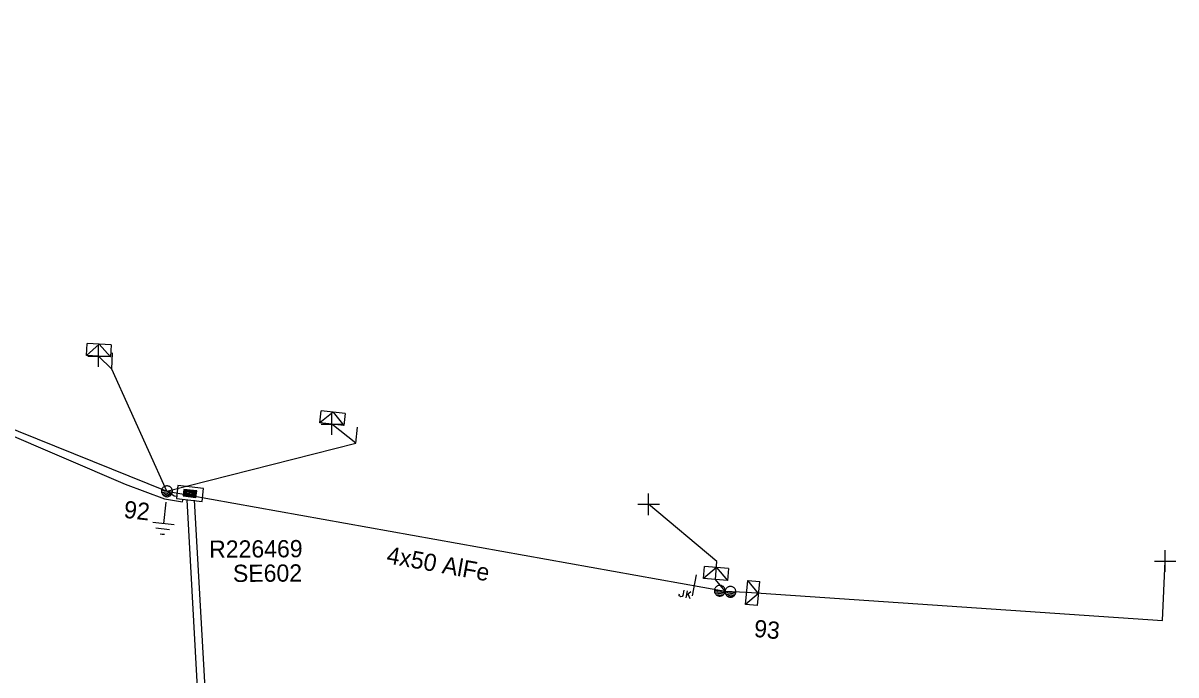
# Model space of a CAD drawing. Extents: x -544780 to -541582, y -1198995 to -1196551.
# Drawn here: x -542510.9 to -542443.9, y -1198250.4 to -1198212.6 of the extents above; entities that cross this region are included whole.
import ezdxf

# ---------------------------------------------------------------- set-up
doc = ezdxf.new("R2010")
doc.units = 0
for name, color, linetype in [('Vrstva 1', 7, 'Continuous'), ('Vrstva 13', 7, 'Continuous'), ('Vrstva 14', 7, 'Continuous'), ('Vrstva 15', 7, 'Continuous'), ('Vrstva 18', 7, 'Continuous'), ('Vrstva 2', 7, 'Continuous'), ('Vrstva 28', 7, 'Continuous'), ('Vrstva 29', 7, 'Continuous'), ('Vrstva 30', 7, 'Continuous'), ('Vrstva 31', 7, 'Continuous'), ('Vrstva 34', 7, 'Continuous'), ('Vrstva 5', 7, 'Continuous'), ('Vrstva 54', 7, 'Continuous'), ('Vrstva 59', 7, 'Continuous'), ('Vrstva 8', 7, 'Continuous'), ('Vrstva 9', 7, 'Continuous')]:
    doc.layers.add(name, color=color, linetype=linetype)

# ---------------------------------------------------------------- blocks, each defined once
blk = doc.blocks.new('NN440')
at = {"layer": 'Vrstva 2'}
for points in [[(0.63, 0), (0.63, 0.06), (0.62, 0.13), (0.6, 0.19), (0.58, 0.25), (0.55, 0.31), (0.51, 0.37), (0.47, 0.42), (0.42, 0.46), (0.37, 0.51), (0.32, 0.54), (0.26, 0.57), (0.2, 0.59), (0.13, 0.61), (0.07, 0.62), (0, 0.63), (-0.06, 0.62), (-0.13, 0.61), (-0.19, 0.59), (-0.26, 0.57), (-0.31, 0.54), (-0.37, 0.51), (-0.42, 0.46), (-0.47, 0.42), (-0.51, 0.37), (-0.54, 0.31), (-0.57, 0.25), (-0.6, 0.19), (-0.62, 0.13), (-0.63, 0.06), (-0.63, 0), (-0.63, -0.07), (-0.62, -0.14), (-0.6, -0.2), (-0.57, -0.26), (-0.54, -0.32), (-0.51, -0.37), (-0.47, -0.43), (-0.42, -0.47), (-0.37, -0.51), (-0.31, -0.55), (-0.26, -0.58), (-0.19, -0.6), (-0.13, -0.62), (-0.06, -0.63), (0, -0.63), (0.07, -0.63), (0.13, -0.62), (0.2, -0.6), (0.26, -0.58), (0.32, -0.55), (0.37, -0.51), (0.42, -0.47), (0.47, -0.43), (0.51, -0.37), (0.55, -0.32), (0.58, -0.26), (0.6, -0.2), (0.62, -0.14), (0.63, -0.07), (0.63, 0)], [(-0.63, 0), (0.63, 0)], [(-0.6, -0.18), (0.57, -0.18)], [(-0.51, -0.32), (0.5, -0.32)], [(-0.37, -0.47), (0.35, -0.47)]]:
    blk.add_lwpolyline(points, dxfattribs=at)
blk = doc.blocks.new('NN450')
at = {"layer": 'Vrstva 2'}
for points in [[(0, 0), (0, 0.07), (-0.01, 0.13), (-0.03, 0.19), (-0.05, 0.25), (-0.08, 0.31), (-0.12, 0.37), (-0.16, 0.42), (-0.21, 0.46), (-0.26, 0.51), (-0.31, 0.54), (-0.37, 0.57), (-0.43, 0.59), (-0.5, 0.61), (-0.56, 0.62), (-0.63, 0.62), (-0.69, 0.62), (-0.75, 0.61), (-0.82, 0.59), (-0.88, 0.57), (-0.94, 0.54), (-0.99, 0.51), (-1.04, 0.46), (-1.09, 0.42), (-1.13, 0.37), (-1.17, 0.31), (-1.2, 0.25), (-1.22, 0.19), (-1.24, 0.13), (-1.25, 0.07), (-1.25, 0), (-1.25, -0.07), (-1.24, -0.13), (-1.22, -0.19), (-1.2, -0.25), (-1.17, -0.31), (-1.13, -0.37), (-1.09, -0.42), (-1.04, -0.46), (-0.99, -0.51), (-0.94, -0.54), (-0.88, -0.57), (-0.82, -0.59), (-0.75, -0.61), (-0.69, -0.62), (-0.62, -0.63), (-0.56, -0.62), (-0.5, -0.61), (-0.43, -0.59), (-0.37, -0.57), (-0.31, -0.54), (-0.26, -0.51), (-0.21, -0.46), (-0.16, -0.42), (-0.12, -0.37), (-0.08, -0.31), (-0.05, -0.25), (-0.03, -0.19), (-0.01, -0.13), (0, -0.07), (0, 0)], [(1.25, 0), (1.25, 0.07), (1.24, 0.13), (1.22, 0.19), (1.2, 0.25), (1.17, 0.31), (1.13, 0.37), (1.09, 0.42), (1.04, 0.46), (0.99, 0.51), (0.94, 0.54), (0.88, 0.57), (0.82, 0.59), (0.75, 0.61), (0.69, 0.62), (0.62, 0.62), (0.56, 0.62), (0.5, 0.61), (0.43, 0.59), (0.37, 0.57), (0.31, 0.54), (0.26, 0.51), (0.21, 0.46), (0.16, 0.42), (0.12, 0.37), (0.08, 0.31), (0.05, 0.25), (0.03, 0.19), (0.01, 0.13), (0, 0.07), (0, 0), (0, -0.07), (0.01, -0.13), (0.03, -0.19), (0.05, -0.25), (0.08, -0.31), (0.12, -0.37), (0.16, -0.42), (0.21, -0.46), (0.26, -0.51), (0.31, -0.54), (0.37, -0.57), (0.43, -0.59), (0.5, -0.61), (0.56, -0.62), (0.63, -0.63), (0.69, -0.62), (0.75, -0.61), (0.82, -0.59), (0.88, -0.57), (0.94, -0.54), (0.99, -0.51), (1.04, -0.46), (1.09, -0.42), (1.13, -0.37), (1.17, -0.31), (1.2, -0.25), (1.22, -0.19), (1.24, -0.13), (1.25, -0.07), (1.25, 0)], [(-1.25, 0), (1.25, 0)], [(-1.23, -0.16), (-0.02, -0.16)], [(-1.16, -0.32), (-0.09, -0.32)], [(-1.03, -0.47), (-0.22, -0.47)], [(0.02, -0.16), (1.23, -0.16)], [(0.09, -0.32), (1.16, -0.32)], [(0.22, -0.47), (1.03, -0.47)]]:
    blk.add_lwpolyline(points, dxfattribs=at)
blk = doc.blocks.new('NN840')
at = {"layer": 'Vrstva 15'}
for points in [[(0.003, 0.619), (0.003, -0.631)], [(-0.745, -0.71), (-0.745, -0.66)], [(-0.538, -0.385), (-0.538, -0.71)], [(-0.332, -0.385), (-0.332, -0.798)], [(-0.332, -0.641), (-0.125, -0.385)], [(-0.263, -0.557), (-0.091, -0.798)], [(-0.73, -0.764), (-0.745, -0.71)], [(-0.657, -0.798), (-0.73, -0.764)], [(-0.627, -0.798), (-0.657, -0.798)], [(-0.558, -0.764), (-0.627, -0.798)], [(-0.538, -0.71), (-0.558, -0.764)]]:
    blk.add_lwpolyline(points, dxfattribs=at)
blk = doc.blocks.new('NN800')
at = {"layer": 'Vrstva 1'}
for points in [[(-0.442, 0.442), (0.442, -0.442)], [(-0.442, -0.442), (0.442, 0.442)]]:
    blk.add_lwpolyline(points, dxfattribs=at)
blk = doc.blocks.new('NN620')
at = {"layer": 'Vrstva 8'}
for points in [[(0.752, 0.004), (-0.748, 0.004)], [(-0.748, 0.004), (-0.748, -0.746)], [(0.752, -0.746), (0.752, 0.004)], [(0.368, -0.18), (-0.376, -0.18)], [(-0.376, -0.18), (-0.376, -0.558)], [(-0.376, -0.558), (0.368, -0.558)], [(0.321, -0.227), (-0.329, -0.227)], [(-0.329, -0.227), (-0.329, -0.51)], [(-0.329, -0.51), (0.321, -0.51)], [(0.274, -0.274), (-0.281, -0.274)], [(-0.281, -0.274), (-0.281, -0.463)], [(-0.281, -0.463), (0.274, -0.463)], [(0.227, -0.321), (-0.234, -0.321)], [(-0.234, -0.321), (-0.234, -0.416)], [(-0.234, -0.416), (0.227, -0.416)], [(-0.193, -0.369), (0.185, -0.369)], [(0.227, -0.416), (0.227, -0.321)], [(0.274, -0.463), (0.274, -0.274)], [(0.321, -0.51), (0.321, -0.227)], [(0.368, -0.558), (0.368, -0.18)], [(-0.748, -0.746), (0.752, -0.746)]]:
    blk.add_lwpolyline(points, dxfattribs=at)
blk = doc.blocks.new('NN630')
at = {"layer": 'Vrstva 9'}
for points in [[(-0.003, -0.7), (-0.703, 0)], [(-0.703, -0.7), (-0.703, 0), (0.697, 0), (0.697, -0.7)], [(-0.003, -0.7), (0.697, 0)], [(-0.703, -0.7), (0.697, -0.7)]]:
    blk.add_lwpolyline(points, dxfattribs=at)
blk = doc.blocks.new('NN810')
at = {"layer": 'Vrstva 14'}
for points in [[(0.004, -0.64), (0.004, -1.89)], [(0.629, -1.89), (-0.621, -1.89)], [(0.388, -2.2), (-0.399, -2.2)], [(0.004, -2.515), (-0.124, -2.515)], [(0.137, -2.515), (0.004, -2.515)]]:
    blk.add_lwpolyline(points, dxfattribs=at)
blk = doc.blocks.new('NN510')
at = {"layer": 'Vrstva 2'}
blk.add_lwpolyline([(0.001, 0.002), (0.001, 0.939)], dxfattribs=at)

msp = doc.modelspace()

# ---------------------------------------------------------------- linework, layer by layer
at = {"layer": 'Vrstva 1'}
for points in [[(-542579.214, -1198212.603), (-542578.383, -1198212.904), (-542558.144, -1198220.225), (-542530.653, -1198228.444), (-542502.529, -1198239.78)], [(-542502.529, -1198239.78), (-542470.119, -1198245.583)]]:
    msp.add_lwpolyline(points, dxfattribs=at)
at = {"layer": 'Vrstva 5'}
for points in [[(-542518.023, -1198243.93), (-542512.462, -1198246.004), (-542512.462, -1198236.378), (-542512.23, -1198236.249), (-542504.957, -1198239.359), (-542502.666, -1198240.21), (-542501.626, -1198240.387), (-542501.597, -1198240.246)], [(-542501.958, -1198240.074), (-542502.119, -1198240.055), (-542502.529, -1198239.78)], [(-542501.367, -1198240.275), (-542500.187, -1198261.761), (-542499.192, -1198271.084), (-542496.934, -1198290.603), (-542493.649, -1198319.853), (-542490.225, -1198351.907), (-542486.981, -1198382.151), (-542483.861, -1198408.973), (-542480.617, -1198439.205), (-542476.757, -1198469.097), (-542473.896, -1198499.184), (-542472.102, -1198520.602), (-542472.829, -1198522.39), (-542472.005, -1198533.989), (-542470.841, -1198553.152), (-542469.907, -1198553.187)], [(-542500.951, -1198240.301), (-542499.717, -1198262.1), (-542498.871, -1198271.111), (-542494.279, -1198270.543), (-542494.243, -1198270.87), (-542498.877, -1198271.437), (-542496.681, -1198290.613), (-542492.219, -1198290.052), (-542492.17, -1198290.426), (-542496.623, -1198291.014), (-542493.3, -1198320.141), (-542489.086, -1198319.916), (-542489.051, -1198320.297), (-542493.243, -1198320.542), (-542489.934, -1198351.75), (-542485.673, -1198351.449), (-542485.617, -1198351.786), (-542489.95, -1198352.081), (-542486.611, -1198382.561)]]:
    msp.add_lwpolyline(points, dxfattribs=at)
at = {"layer": 'Vrstva 54'}
msp.add_lwpolyline([(-542502.529, -1198239.779), (-542505.738, -1198232.688), (-542506.507, -1198231.933)], dxfattribs=at)
at = {"layer": 'Vrstva 59'}
for points in [[(-542470.119, -1198245.583), (-542470.684, -1198244.894), (-542470.591, -1198243.849), (-542474.559, -1198240.535)], [(-542470.119, -1198245.583), (-542468.873, -1198245.643), (-542444.729, -1198247.277), (-542444.567, -1198243.831)]]:
    msp.add_lwpolyline(points, dxfattribs=at)
at = {"layer": 'Vrstva 8'}
msp.add_lwpolyline([(-542502.529, -1198239.78), (-542491.572, -1198236.988), (-542492.957, -1198235.886)], dxfattribs=at)

# ---------------------------------------------------------------- block references
at = {"layer": 'Vrstva 13'}
for p, rotation in [((-542505.739, -1198232.689), -3.1221304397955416), ((-542491.573, -1198236.988), -6.413169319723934)]:
    msp.add_blockref('NN510', p, dxfattribs=dict(at, rotation=rotation))
at = {"layer": 'Vrstva 13', "xscale": 0.5}
for name, p, yscale, rotation in [('NN440', (-542502.529, -1198239.779), 0.49999999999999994, -6.41316944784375), ('NN450', (-542470.119, -1198245.583), 0.5, -5.795250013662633)]:
    msp.add_blockref(name, p, dxfattribs=dict(at, yscale=yscale, rotation=rotation))
at = {"layer": 'Vrstva 15', "rotation": -6.4131694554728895}
msp.add_blockref('NN810', (-542502.528, -1198239.78), dxfattribs=at)
at = {"layer": 'Vrstva 18', "rotation": -10.928302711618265}
msp.add_blockref('NN840', (-542471.921, -1198245.235), dxfattribs=at)
at = {"layer": 'Vrstva 28', "rotation": -6.413169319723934}
msp.add_blockref('NN620', (-542501.147, -1198239.539), dxfattribs=at)
at = {"layer": 'Vrstva 31'}
for p, rotation in [((-542506.507, -1198231.933), 176.87786942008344), ((-542492.957, -1198235.886), 173.58683054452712), ((-542470.684, -1198244.894), 175.3859443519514), ((-542468.873, -1198245.643), 84.2047500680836)]:
    msp.add_blockref('NN630', p, dxfattribs=dict(at, rotation=rotation))
at = {"layer": 'Vrstva 34'}
for p, rotation in [((-542506.507, -1198231.933), 45), ((-542492.957, -1198235.886), 45.00000009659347), ((-542474.559, -1198240.535), 45), ((-542444.567, -1198243.831), 45)]:
    msp.add_blockref('NN800', p, dxfattribs=dict(at, rotation=rotation))

# ---------------------------------------------------------------- texts
at = {"layer": 'Vrstva 14'}
for s, rotation, p in [('92', 353.587, (-542505.067, -1198241.313)), ('93', 354.205, (-542468.475, -1198248.223))]:
    msp.add_text(s, height=1, rotation=rotation, dxfattribs=at).set_placement(p)
at = {"layer": 'Vrstva 2'}
msp.add_text('4x50 AlFe', height=1, rotation=349.849, dxfattribs=at).set_placement((-542489.822, -1198243.949))
at = {"layer": 'Vrstva 29'}
msp.add_text('R226469', height=1, rotation=0.349, dxfattribs=at).set_placement((-542500.078, -1198243.64))
at = {"layer": 'Vrstva 30'}
msp.add_text('SE602', height=1, rotation=0.349, dxfattribs=at).set_placement((-542498.696, -1198245.044))

doc.saveas('drawing.dxf')
